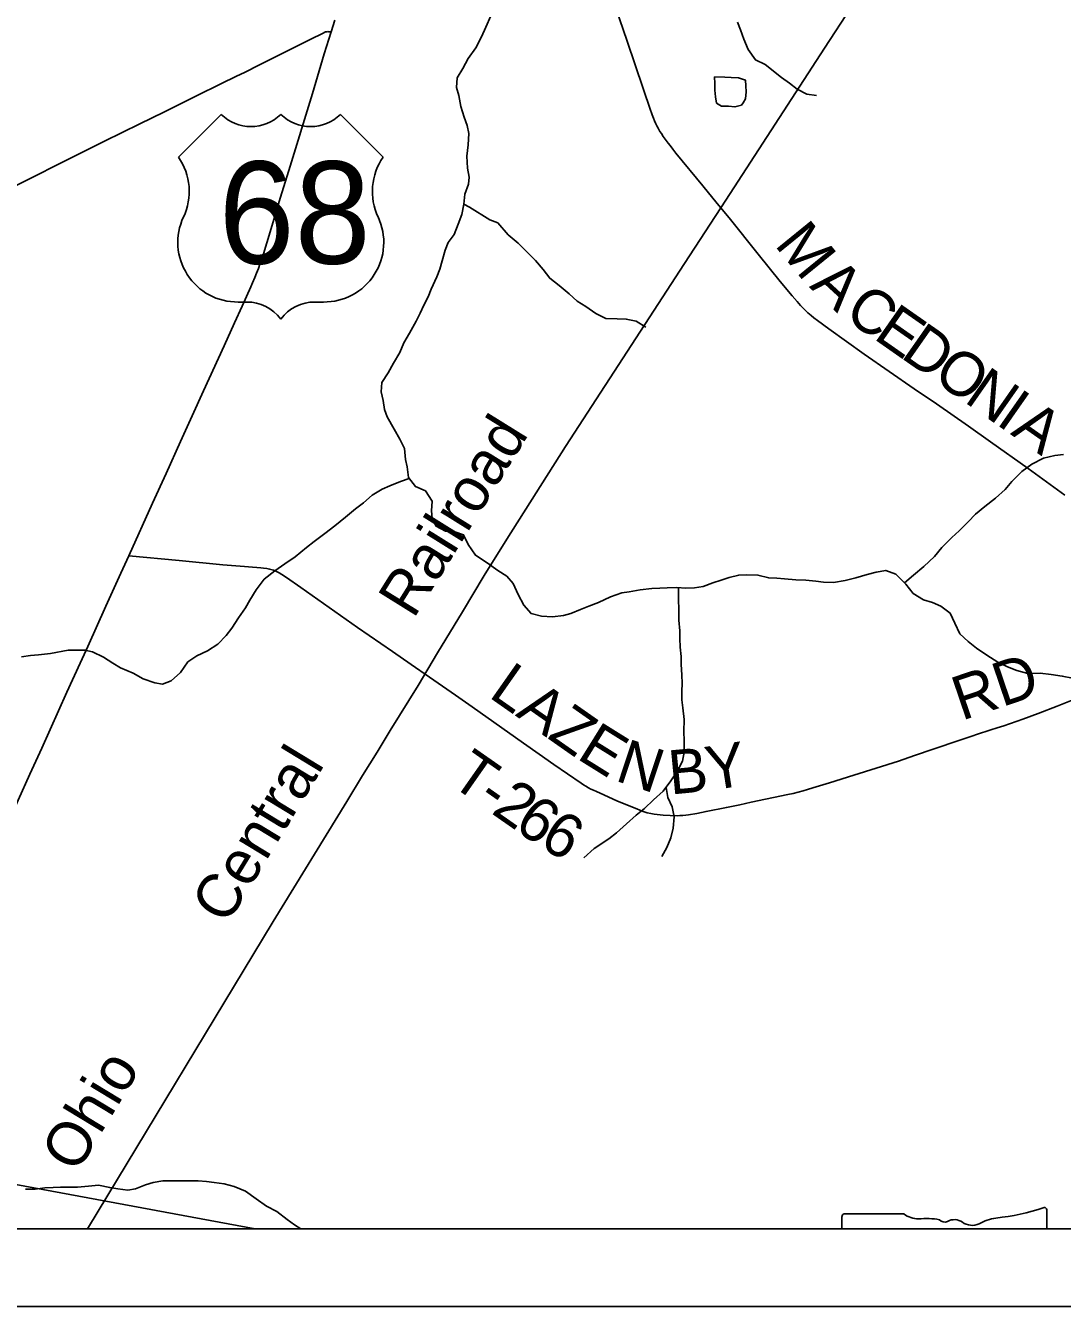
# Model space of a CAD drawing. Extents: x 0 to 34, y 0 to 22.
# Drawn here: x 3.586 to 4.922, y 14 to 15.651 of the extents above; entities that cross this region are included whole.
import ezdxf

# ---------------------------------------------------------------- set-up
doc = ezdxf.new("R2010")
doc.units = 0
for name, color, linetype in [('GM_X_Corporation_Text', 7, 'Continuous'), ('GM_X_County_Road', 7, 'Continuous'), ('GM_X_County_Road_Text', 7, 'Continuous'), ('GM_X_Minor_Lake', 7, 'Continuous'), ('GM_X_Minor_River', 7, 'Continuous'), ('GM_X_Rail_Line', 7, 'Continuous'), ('GM_X_Rail_Line_Text', 7, 'Continuous'), ('GM_X_Township_Road', 7, 'Continuous'), ('GM_X_Township_Road_Text', 7, 'Continuous'), ('GM_X_US_Location', 7, 'Continuous'), ('GM_X_US_Route', 7, 'Continuous'), ('GM_X_US_Shield', 7, 'Continuous'), ('SH_Data', 7, 'Continuous')]:
    doc.layers.add(name, color=color, linetype=linetype)

msp = doc.modelspace()

# ---------------------------------------------------------------- linework, layer by layer
at = {"layer": 'GM_X_Corporation_Text'}
msp.add_line((4.7179, 14.1192), (4.6406, 14.1192), dxfattribs=at)
msp.add_lwpolyline([(4.638, 14.1157), (4.638, 14.1), (4.9017, 14.1), (4.9017, 14.1243)], dxfattribs=at)
for centre, radius, start, end in [((4.6411, 14.1161), 0.00305, 98.978, 188.5967), ((4.7362, 14.1424), 0.0296, 231.6404, 271.1117), ((4.7461, 14.0068), 0.1064, 80.4867, 94.9883), ((4.7828, 14.094), 0.0178, 54.4667, 119.1411), ((4.8435, 14.058), 0.0563, 97.3462, 120.7689), ((4.8078, 14.392), 0.2796, 275.8445, 288.9065), ((4.8988, 14.1246), 0.00294, 355.0978, 97.738), ((4.7702, 14.1172), 0.00855, 219.7921, 297.1024), ((4.8057, 14.1258), 0.0214, 233.8562, 294.8282)]:
    msp.add_arc(centre, radius, start, end, dxfattribs=at)
at = {"layer": 'GM_X_County_Road'}
for points in [[(4.3429, 15.6846), (4.3609, 15.6317), (4.3721, 15.5988), (4.3912, 15.5417), (4.3925, 15.5383), (4.3935, 15.5355), (4.3951, 15.5313), (4.3966, 15.5276), (4.3982, 15.5239), (4.3995, 15.5213), (4.401, 15.5184), (4.4034, 15.5141), (4.4053, 15.5113), (4.4078, 15.5074), (4.4102, 15.5042), (4.4141, 15.499), (4.4166, 15.4958), (4.4203, 15.4911), (4.4241, 15.4863), (4.4587, 15.4439), (4.4772, 15.4214), (4.4925, 15.4026), (4.5299, 15.3561), (4.5585, 15.3209), (4.5739, 15.3022), (4.5801, 15.2949), (4.5824, 15.2923), (4.5846, 15.2899), (4.587, 15.2873), (4.5891, 15.2852), (4.5914, 15.283), (4.5942, 15.2804), (4.5983, 15.2769), (4.6017, 15.2741), (4.6065, 15.2703), (4.621, 15.2596), (4.6666, 15.2271), (4.7309, 15.1826), (4.7597, 15.163), (4.8009, 15.1342), (4.8293, 15.114), (4.878, 15.0796), (4.9253, 15.0455)], [(3.5722, 15.4438), (3.6528, 15.4839), (3.6879, 15.5014), (3.7336, 15.5238), (3.7642, 15.5391), (3.8054, 15.5595), (3.8388, 15.576), (3.8573, 15.5849), (3.869, 15.5907), (3.8868, 15.5995), (3.9024, 15.6072), (3.9357, 15.624), (3.9529, 15.6326), (3.9695, 15.6408), (3.9716, 15.6419), (3.9726, 15.6423), (3.9735, 15.6426), (3.9744, 15.6427), (3.9756, 15.6428), (3.9771, 15.6427), (3.9799, 15.6426)]]:
    msp.add_lwpolyline(points, dxfattribs=at)
at = {"layer": 'GM_X_Minor_Lake'}
for points in [[(4.4738, 15.5844), (4.4744, 15.576), (4.4743, 15.5673), (4.4749, 15.5589), (4.4763, 15.5506), (4.4827, 15.5467), (4.4918, 15.5466), (4.5001, 15.5457), (4.5085, 15.5478), (4.5105, 15.5512)], [(4.5105, 15.5512), (4.5136, 15.5561), (4.5144, 15.5652), (4.5142, 15.5728), (4.5135, 15.5804), (4.5045, 15.5832), (4.4954, 15.5837), (4.487, 15.5842), (4.4738, 15.5844)]]:
    msp.add_lwpolyline(points, dxfattribs=at)
at = {"layer": 'GM_X_Minor_River'}
for points in [[(4.1856, 15.6631), (4.1793, 15.6484), (4.1738, 15.6359), (4.1664, 15.622), (4.1564, 15.6081), (4.1497, 15.5953), (4.1424, 15.5832), (4.1414, 15.5707), (4.1443, 15.5604), (4.1468, 15.5463), (4.1511, 15.5326), (4.1551, 15.5219), (4.1572, 15.5113), (4.1563, 15.4968), (4.1545, 15.4821), (4.1555, 15.4669), (4.1579, 15.4554), (4.1567, 15.446), (4.1523, 15.4335), (4.151, 15.4206), (4.1481, 15.407), (4.1434, 15.3945), (4.1383, 15.3813), (4.1306, 15.3712), (4.1266, 15.361), (4.123, 15.3473), (4.1198, 15.3368), (4.1159, 15.3266), (4.1088, 15.3107), (4.1049, 15.3009), (4.0994, 15.2903), (4.0947, 15.2801), (4.0893, 15.2696), (4.0807, 15.2541), (4.0737, 15.2417), (4.0682, 15.2293), (4.0604, 15.2157), (4.0534, 15.2029), (4.0453, 15.1908), (4.0444, 15.1787), (4.0468, 15.1673), (4.0486, 15.1559), (4.0522, 15.1463), (4.0611, 15.1303), (4.0685, 15.1176), (4.0744, 15.1054), (4.0757, 15.0913)], [(4.5036, 15.655), (4.5073, 15.6451), (4.5116, 15.6332), (4.5171, 15.6199), (4.5264, 15.6064), (4.5392, 15.6006), (4.5602, 15.5836), (4.5703, 15.5762), (4.5801, 15.5685), (4.5929, 15.5623), (4.605, 15.5606)], [(4.1509, 15.4202), (4.1581, 15.4167), (4.1844, 15.4004), (4.1946, 15.3965), (4.2081, 15.3811), (4.2208, 15.3703), (4.2309, 15.3603), (4.2432, 15.348), (4.2529, 15.3361), (4.2615, 15.3249), (4.2735, 15.3157), (4.2866, 15.3049), (4.2967, 15.2952), (4.308, 15.2886), (4.3211, 15.2793), (4.3339, 15.2731), (4.3483, 15.2725), (4.36, 15.2724), (4.3729, 15.2695), (4.3853, 15.2618)], [(4.0757, 15.0913), (4.0778, 15.0818), (4.0795, 15.0681), (4.0885, 15.0566), (4.1013, 15.0508), (4.1102, 15.0377), (4.1092, 15.0252), (4.1099, 15.0153), (4.1154, 15.0054), (4.1271, 14.9992), (4.1407, 14.9978), (4.1505, 14.9943), (4.1564, 14.9817), (4.1657, 14.9679), (4.1807, 14.9582), (4.1946, 14.9485), (4.2062, 14.9411), (4.2144, 14.9315), (4.221, 14.9174), (4.2281, 14.9036), (4.2374, 14.8929), (4.251, 14.8893), (4.265, 14.8887), (4.2794, 14.8904), (4.2889, 14.8929), (4.3012, 14.8981), (4.3118, 14.9025), (4.3244, 14.9069), (4.3397, 14.9146), (4.3542, 14.9194), (4.3637, 14.9208), (4.3781, 14.9236), (4.3929, 14.9253), (4.4032, 14.9255), (4.4126, 14.9258), (4.4252, 14.9264), (4.4369, 14.9255), (4.4479, 14.9261), (4.4593, 14.9278), (4.4715, 14.9326), (4.4822, 14.9358), (4.4925, 14.9395), (4.505, 14.9424), (4.5145, 14.9426), (4.5297, 14.9424), (4.5437, 14.9388), (4.5539, 14.9383), (4.5641, 14.9374), (4.5785, 14.9364), (4.5914, 14.9359), (4.6043, 14.9346), (4.6141, 14.9333), (4.627, 14.9327), (4.6422, 14.9356), (4.6559, 14.9388), (4.6704, 14.9432), (4.6822, 14.946), (4.6943, 14.9485), (4.7075, 14.9438), (4.7202, 14.9307), (4.7295, 14.9188), (4.7431, 14.9107), (4.7548, 14.9071), (4.7653, 14.9024), (4.7773, 14.8935), (4.7836, 14.8805), (4.7898, 14.8667), (4.8007, 14.8567), (4.8115, 14.8482), (4.8247, 14.8393), (4.8386, 14.83), (4.8514, 14.8241), (4.8631, 14.8194), (4.8774, 14.8158), (4.8934, 14.8161)], [(4.7184, 14.9326), (4.7303, 14.9423), (4.7433, 14.9535), (4.7571, 14.9663), (4.7668, 14.9779), (4.7795, 14.991), (4.7891, 14.9996), (4.8006, 15.0112), (4.8099, 15.021), (4.8222, 15.0307), (4.8356, 15.0415), (4.8483, 15.0527), (4.8567, 15.0629), (4.8698, 15.076), (4.8825, 15.0853), (4.8976, 15.0931)], [(4.8976, 15.0931), (4.9122, 15.0964), (4.9233, 15.0977)], [(4.0804, 15.067), (4.0692, 15.063), (4.0555, 15.0575), (4.0456, 15.053), (4.0326, 15.0452), (4.0214, 15.0355), (4.0111, 15.0277), (3.9984, 15.0172), (3.9846, 15.0057), (3.9716, 14.996), (3.9581, 14.9859), (3.9482, 14.9781), (3.9336, 14.9661), (3.9202, 14.9568), (3.9072, 14.9479), (3.8934, 14.937), (3.8833, 14.9235), (3.8751, 14.9103), (3.8697, 14.9002), (3.8604, 14.8874), (3.8519, 14.8742), (3.8445, 14.8644), (3.8341, 14.8532), (3.8204, 14.8446), (3.807, 14.8384), (3.7951, 14.8306), (3.7858, 14.817), (3.7739, 14.8062), (3.7625, 14.8018), (3.7526, 14.8034), (3.7376, 14.8089), (3.7248, 14.816), (3.7086, 14.823), (3.6988, 14.8288), (3.6868, 14.8366), (3.6725, 14.8436), (3.6626, 14.8457), (3.6528, 14.8458), (3.641, 14.8456), (3.6182, 14.8413), (3.603, 14.8396), (3.5924, 14.8386), (3.581, 14.8369)], [(4.4276, 14.9262), (4.4276, 14.9112), (4.4278, 14.8975), (4.428, 14.8842), (4.4289, 14.8705), (4.4291, 14.8606), (4.4297, 14.8496), (4.4307, 14.8375), (4.4309, 14.8272), (4.4315, 14.8139), (4.4321, 14.8025), (4.4316, 14.7927), (4.4318, 14.7816), (4.4328, 14.7714), (4.4345, 14.7565), (4.4342, 14.741), (4.4348, 14.7288), (4.4346, 14.7144), (4.4325, 14.7027), (4.4255, 14.6891), (4.4174, 14.6771), (4.4077, 14.6639), (4.3954, 14.6527), (4.3835, 14.6418), (4.3728, 14.6332), (4.3605, 14.622), (4.3474, 14.6101), (4.3378, 14.6026), (4.3187, 14.5899), (4.3056, 14.578)], [(4.8934, 14.8161), (4.9077, 14.8144), (4.9217, 14.8123), (4.935, 14.8095)], [(4.4113, 14.6687), (4.4137, 14.6558), (4.4192, 14.6436), (4.422, 14.6307), (4.4207, 14.6163), (4.4175, 14.6038), (4.4124, 14.5913), (4.4061, 14.5796)], [(3.5863, 14.1512), (3.5984, 14.151), (3.6109, 14.1527), (3.6219, 14.153), (3.6314, 14.1536), (3.642, 14.1538), (3.653, 14.1537), (3.6671, 14.155), (3.68, 14.1563), (3.6947, 14.1531), (3.705, 14.1515), (3.7178, 14.1498), (3.7277, 14.1515), (3.7407, 14.1567), (3.7506, 14.1596), (3.7631, 14.1617), (3.7787, 14.1618), (3.7934, 14.1616), (3.8086, 14.1618), (3.8192, 14.1609), (3.8291, 14.1596), (3.8419, 14.1579), (3.8551, 14.1543), (3.8695, 14.1485), (3.8834, 14.1384), (3.8965, 14.1291), (3.91, 14.1221), (3.9232, 14.112), (3.9329, 14.1051), (3.941, 14.1)]]:
    msp.add_lwpolyline(points, dxfattribs=at)
at = {"layer": 'GM_X_Rail_Line'}
msp.add_lwpolyline([(3.6659, 14.1), (3.9054, 14.4958), (4.0003, 14.6507), (4.0205, 14.684), (4.0392, 14.7143), (4.056, 14.7423), (4.0918, 14.8003), (4.1171, 14.8421), (4.1493, 14.895), (4.1772, 14.9418), (4.2062, 14.9888), (4.2819, 15.1081), (4.435, 15.3439), (4.4884, 15.4256), (4.6156, 15.6215), (4.8241, 15.9416)], dxfattribs=at)
at = {"layer": 'GM_X_Township_Road'}
for points in [[(3.7277, 16.7873), (3.6691, 16.5264), (3.3385, 15.3189), (3.2153, 14.8228), (3.0598, 14.2522), (3.3693, 14.1947), (3.882, 14.1), (5.5061, 14.1), (5.6307, 14.246), (5.7089, 14.3412), (6.2381, 14.9624), (6.7874, 15.6255), (6.8121, 15.6375), (7.6646, 16.0363), (8.8399, 16.5839), (8.8447, 16.5834), (8.8816, 16.5789), (8.8995, 16.5764), (8.9, 16.5763), (8.9, 19.1426)], [(3.7192, 14.9671), (3.7843, 14.9612), (3.8405, 14.9556), (3.8684, 14.9534), (3.8733, 14.953), (3.8895, 14.9518), (3.8928, 14.9513), (3.897, 14.9508), (3.9005, 14.9501), (3.9055, 14.9486), (3.9093, 14.9471), (3.913, 14.9453), (3.9165, 14.9431), (3.9225, 14.9393), (3.9409, 14.9266), (4.014, 14.875), (4.059, 14.8439), (4.0829, 14.8272), (4.1065, 14.811), (4.1402, 14.7877), (4.1616, 14.7728), (4.2279, 14.7256), (4.2478, 14.7117), (4.2666, 14.6985), (4.3018, 14.6741), (4.3049, 14.6722), (4.3081, 14.6702), (4.3115, 14.6684), (4.3146, 14.6667), (4.318, 14.6652), (4.3218, 14.6634), (4.3264, 14.6613), (4.348, 14.6517), (4.3703, 14.6423), (4.3738, 14.641), (4.3777, 14.6395), (4.3819, 14.6379), (4.3872, 14.6362), (4.3919, 14.6351), (4.3959, 14.6345), (4.3998, 14.6339), (4.4038, 14.6334), (4.4078, 14.6329), (4.4165, 14.6324), (4.4257, 14.6323), (4.4292, 14.6325), (4.4331, 14.6328), (4.4368, 14.6332), (4.4404, 14.6336), (4.4508, 14.6353), (4.463, 14.6378), (4.4891, 14.6431), (4.5062, 14.6465), (4.5208, 14.6496), (4.5682, 14.6595), (4.5752, 14.6611), (4.5815, 14.6626), (4.5881, 14.6644), (4.5934, 14.6659), (4.6004, 14.6681), (4.6219, 14.6747), (4.6534, 14.6845), (4.7108, 14.7028), (4.7314, 14.7098), (4.7555, 14.7181), (4.7899, 14.7297), (4.7949, 14.7314), (4.8001, 14.7332), (4.8178, 14.7391), (4.8232, 14.7409), (4.8296, 14.743), (4.838, 14.7457), (4.8463, 14.7483), (4.8537, 14.7509), (4.8639, 14.7543), (4.871, 14.7569), (4.8907, 14.764), (4.9151, 14.7733), (4.9347, 14.7812)]]:
    msp.add_lwpolyline(points, dxfattribs=at)
msp.add_lwpolyline([(2.3933, 14.1), (3.882, 14.1), (3.3693, 14.1947), (3.0598, 14.2522), (2.4714, 14.3654)], close=True, dxfattribs=at)
at = {"layer": 'GM_X_US_Route'}
msp.add_lwpolyline([(3.5616, 14.6188), (3.5918, 14.6857), (3.6074, 14.7195), (3.6396, 14.7916), (3.6665, 14.8503), (3.6898, 14.9025), (3.7091, 14.9449), (3.7192, 14.9671), (3.7498, 15.0349), (3.7673, 15.0734), (3.786, 15.1147), (3.8008, 15.1475), (3.8156, 15.1797), (3.842, 15.238), (3.8555, 15.2673), (3.8654, 15.2888), (3.8764, 15.3138), (3.8786, 15.3191), (3.8814, 15.3258), (3.8839, 15.3316), (3.8862, 15.3377), (3.8882, 15.3433), (3.8898, 15.348), (3.8926, 15.3563), (3.9013, 15.3848), (3.9144, 15.4282), (3.9254, 15.4638), (3.9557, 15.5631), (3.9711, 15.6142), (3.9799, 15.6426), (3.9845, 15.6576)], dxfattribs=at)
at = {"layer": 'GM_X_US_Shield'}
for p, q in [((3.8381, 15.536), (3.7832, 15.4811)), ((4.0469, 15.4811), (3.992, 15.536)), ((3.8601, 15.2943), (3.8711, 15.2943)), ((3.959, 15.2943), (3.97, 15.2943))]:
    msp.add_line(p, q, dxfattribs=at)
for centre, radius, start, end in [((3.8766, 15.5752), 0.0549, 225.573, 314.427), ((3.9535, 15.5752), 0.0549, 225.573, 314.427), ((3.7202, 15.4369), 0.0769, 334.5471, 35.0009), ((4.1099, 15.4369), 0.0769, 144.9991, 205.4529), ((3.8593, 15.3712), 0.0769, 154.8319, 270.6383), ((3.9708, 15.3712), 0.0769, 269.3617, 25.1681), ((3.8711, 15.2394), 0.0549, 36.8699, 90), ((3.959, 15.2394), 0.0549, 90, 143.1301)]:
    msp.add_arc(centre, radius, start, end, dxfattribs=at)
at = {"layer": 'SH_Data'}
for p, q in [((2.1, 14.1), (8.9, 14.1)), ((2, 14), (9, 14))]:
    msp.add_line(p, q, dxfattribs=at)

# ---------------------------------------------------------------- texts
at = {"layer": 'GM_X_County_Road_Text'}
for s, rotation, p in [('M', 309.1199, (4.55, 15.3681)), ('A', 317.3582, (4.595, 15.3138)), ('C', 325.5378, (4.6387, 15.2744)), ('E', 325.0547, (4.6771, 15.248)), ('D', 325.0549, (4.7119, 15.2237)), ('O', 325.052, (4.7529, 15.1951)), ('N', 325.0531, (4.7939, 15.1664)), ('I', 325.0585, (4.8349, 15.1378)), ('A', 325.051, (4.854, 15.1244))]:
    msp.add_text(s, height=0.0568, rotation=rotation, dxfattribs=at).set_placement(p)
at = {"layer": 'GM_X_Rail_Line_Text'}
for s, rotation, p in [('Railroad', 58.0893, (4.086, 14.8849)), ('Central', 58.6781, (3.8454, 14.4902)), ('Ohio', 58.8149, (3.6519, 14.17))]:
    msp.add_text(s, height=0.05663, rotation=rotation, dxfattribs=at).set_placement(p)
at = {"layer": 'GM_X_Township_Road_Text'}
for s, height, rotation, p in [('L', 0.0568, 324.9595, (4.1814, 14.7862)), ('RD', 0.05682, 18.7272, (4.7921, 14.7545)), ('A', 0.0568, 324.958, (4.2162, 14.7618)), ('Z', 0.0568, 324.9793, (4.2572, 14.7331)), ('E', 0.0568, 328.0793, (4.2948, 14.7068)), ('N', 0.0568, 341.6234, (4.3441, 14.6781)), ('Y', 0.0568, 8.9773, (4.4673, 14.6644)), ('T', 0.0568, 325.0178, (4.1308, 14.6741)), ('B', 0.0568, 5.4628, (4.417, 14.6595)), ('2', 0.0568, 325.1061, (4.1848, 14.6363)), ('-', 0.0568, 325.0345, (4.1656, 14.6497)), ('6', 0.0568, 325.3847, (4.2137, 14.6161)), ('6', 0.0568, 329.3279, (4.2461, 14.5939))]:
    msp.add_text(s, height=height, rotation=rotation, dxfattribs=at).set_placement(p)
at = {"layer": 'GM_X_US_Location'}
for s in ['0', '/']:
    msp.add_text(s, height=0.000189, dxfattribs=at).set_placement((3.915, 15.4086))
msp.add_text('68', height=0.000189, rotation=0, dxfattribs=at).set_placement((3.8759, 15.3694))
at = {"layer": 'GM_X_US_Shield'}
msp.add_text('68', height=0.13184, dxfattribs=at).set_placement((3.8348, 15.3437))

doc.saveas('drawing.dxf')
